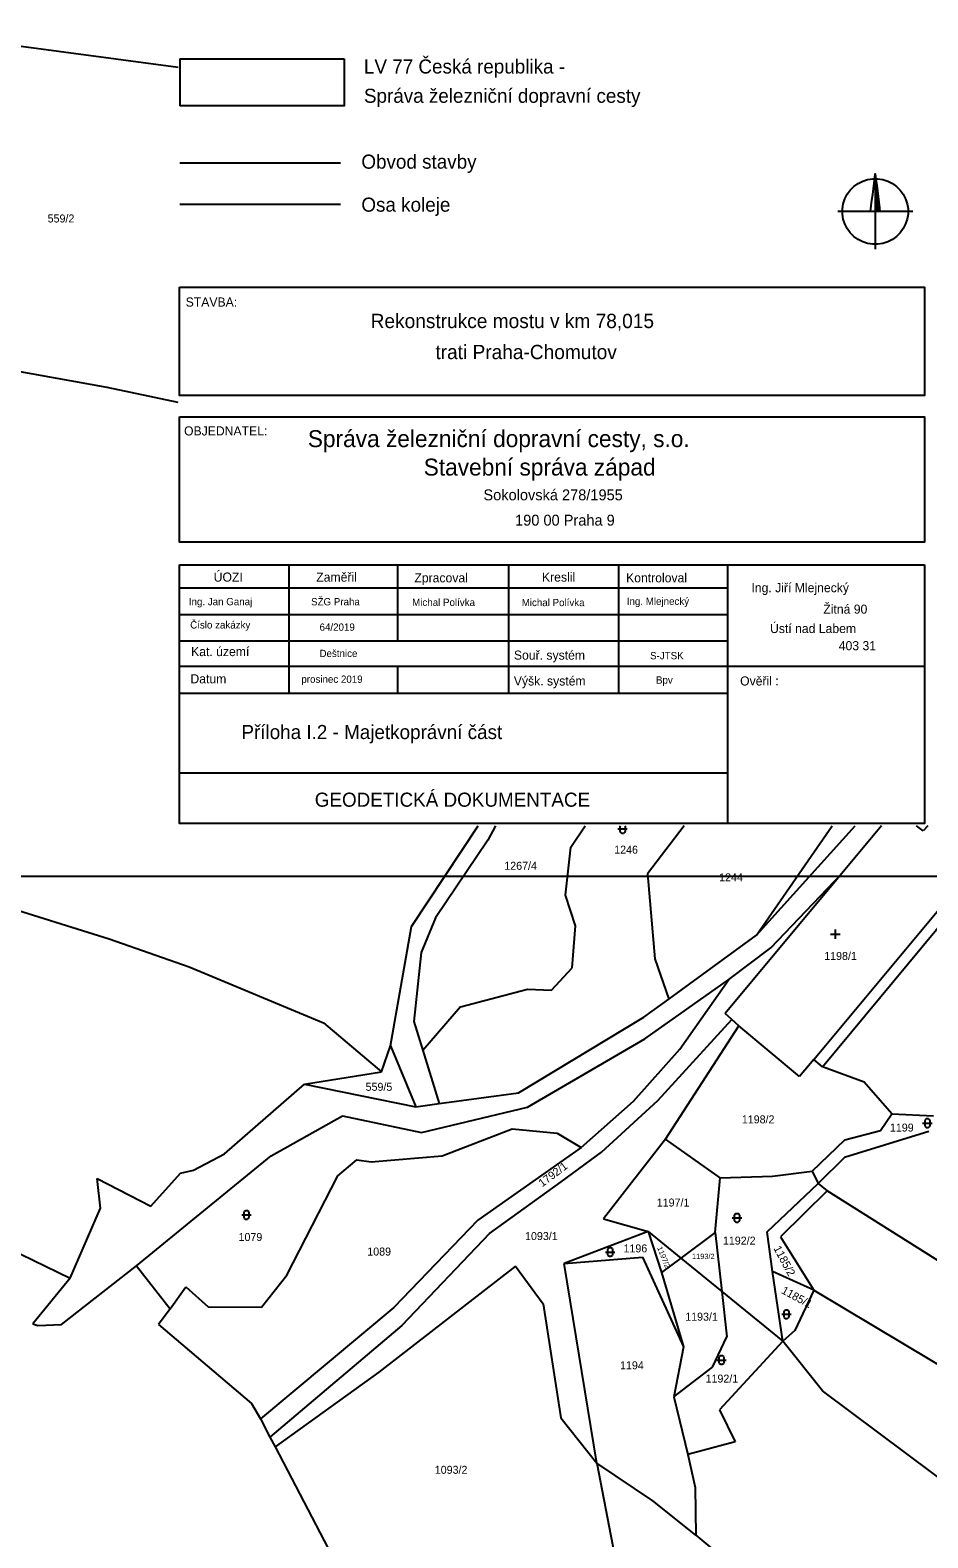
# Model space of a CAD drawing. Extents: x -799786 to -795190, y -1021716 to -1017834.
# Drawn here: x -798625.3 to -798434.2, y -1019350.1 to -1019029 of the extents above; entities that cross this region are included whole.
import ezdxf

# ---------------------------------------------------------------- set-up
doc = ezdxf.new("R2010")
doc.units = 0
for name, color, linetype in [('Default', 7, 'Continuous'), ('KN_HRANICE', 7, 'Continuous'), ('KN_KULTURY', 7, 'Continuous'), ('KN_PARCELY', 7, 'Continuous'), ('LEGENDA', 7, 'Continuous'), ('tabulka', 7, 'Continuous')]:
    doc.layers.add(name, color=color, linetype=linetype)

# ---------------------------------------------------------------- blocks, each defined once
blk = doc.blocks.new('315')
at = {"layer": 'Default'}
for p, q in [((-1, 1), (1, 1)), ((0, 0), (0, 2))]:
    blk.add_line(p, q, dxfattribs=at)
blk = doc.blocks.new('316')
at = {"layer": 'Default'}
for points in [[(-1, 1), (0.27, 1), (1, 1)], [(-0.5, 1.5), (-0.4, 1.79), (-0.15, 1.97), (0.16, 1.97), (0.41, 1.79), (0.51, 1.5), (0.51, 0.5), (0.41, 0.21), (0.16, 0.03), (-0.15, 0.03), (-0.4, 0.21), (-0.5, 0.5), (-0.5, 1.5)]]:
    blk.add_lwpolyline(points, dxfattribs=at)
blk = doc.blocks.new('SEVER')
at = {"layer": 'Default'}
for points in [[(5.5, 69.8), (16.3, 68.1), (26.7, 64.7), (36.5, 59.7), (45.4, 53.2), (53.2, 45.4), (59.7, 36.5), (64.7, 26.7), (68.1, 16.3), (69.8, 5.5), (69.8, -5.5), (68.1, -16.3), (64.7, -26.7), (59.7, -36.5), (53.2, -45.4), (45.4, -53.2), (36.5, -59.7), (26.7, -64.7), (16.3, -68.1), (5.5, -69.8), (-5.5, -69.8), (-16.3, -68.1), (-26.7, -64.7), (-36.5, -59.7), (-45.4, -53.2), (-53.2, -45.4), (-59.7, -36.5), (-64.7, -26.7), (-68.1, -16.3), (-69.8, -5.5), (-69.8, 5.5), (-68.1, 16.3), (-64.7, 26.7), (-59.7, 36.5), (-53.2, 45.4), (-45.4, 53.2), (-36.5, 59.7), (-26.7, 64.7), (-16.3, 68.1), (-5.5, 69.8), (5.5, 69.8)], [(-10, 0), (-8.5, 12), (-7, 24), (-5.5, 36), (-4, 48), (-2.5, 60), (-1, 72), (0, 80), (1.5, 68), (3, 56), (4.5, 44), (6, 32), (7.5, 20), (9, 8), (10, 0), (9.2, 0.8), (9.2, 5.6), (8.4, 12), (8.4, 0.8), (7.6, 0.8), (7.6, 13.5), (7.6, 18.4), (6.8, 24.8), (6.8, 12.1), (6.8, 0.8), (6, 0.8), (6, 13.5), (6, 26.2), (6, 31.2), (5.2, 36.8), (5.2, 24.1), (5.2, 11.4), (5.2, 0.8), (4.4, 0.8), (4.4, 13.5), (4.4, 26.2), (4.4, 38.9), (4.4, 43.2), (3.6, 50.4), (3.6, 37.7), (3.6, 25), (3.6, 12.3), (3.6, 0.8), (2.8, 0.8), (2.8, 13.5), (2.8, 26.2), (2.8, 38.9), (2.8, 51.6), (2.8, 56), (2, 63.2), (2, 50.5), (2, 37.8), (2, 25.1), (2, 12.4), (2, 0.8), (1.2, 0.8), (1.2, 13.5), (1.2, 26.2), (1.2, 38.9), (1.2, 51.6), (1.2, 64.3), (1.2, 69.6), (0.4, 76), (0.4, 63.3), (0.4, 50.6), (0.4, 37.9), (0.4, 25.2), (0.4, 12.5), (0.4, 0.8)], [(0, 80), (0, 67.3), (0, 54.6), (0, 41.9), (0, 29.2), (0, 16.5), (0, 3.8), (0, -8.9), (0, -21.6), (0, -34.3), (0, -47), (0, -59.7), (0, -72.4), (0, -80)], [(80, 0), (67.3, 0), (54.6, 0), (41.9, 0), (29.2, 0), (16.5, 0), (3.8, 0), (-8.9, 0), (-21.6, 0), (-34.3, 0), (-47, 0), (-59.7, 0), (-72.4, 0), (-80, 0)]]:
    blk.add_lwpolyline(points, dxfattribs=at)

msp = doc.modelspace()

# ---------------------------------------------------------------- linework, layer by layer
at = {"layer": 'KN_HRANICE'}
for p, q in [((-798650, -1019029.38), (-798593.84, -1019036.93)), ((-798608.96, -1019105.11), (-798639.62, -1019099.64)), ((-798593.84, -1019108.35), (-798608.96, -1019105.11)), ((-798544.17, -1019219.92), (-798529.93, -1019198.47)), ((-798526.27, -1019198.47), (-798527.91, -1019201.56)), ((-798510.21, -1019203), (-798507.21, -1019198.47)), ((-798486.07, -1019198.47), (-798493.93, -1019208.72)), ((-798470.68, -1019221.78), (-798449.69, -1019198.47)), ((-798470.68, -1019221.78), (-798454.57, -1019198.47)), ((-798444.09, -1019198.47), (-798452.63, -1019208.73)), ((-798435.21, -1019199.56), (-798436.61, -1019198.47)), ((-798434.24, -1019198.47), (-798435.21, -1019199.56)), ((-798527.91, -1019201.56), (-798539.04, -1019218.08)), ((-798511.35, -1019213.22), (-798510.21, -1019203)), ((-798493.93, -1019208.72), (-798492.37, -1019226.82)), ((-798452.63, -1019208.73), (-798477.35, -1019238.45)), ((-798467.68, -1019224.43), (-798452.63, -1019208.73)), ((-798458.53, -1019248.28), (-798425.19, -1019208.25)), ((-798641.03, -1019212.36), (-798608.55, -1019222.56)), ((-798509.26, -1019219.75), (-798511.35, -1019213.22)), ((-798456.62, -1019249.78), (-798429.28, -1019216.81)), ((-798548.65, -1019245.36), (-798544.17, -1019219.92)), ((-798539.04, -1019218.08), (-798542.11, -1019225.49)), ((-798509.93, -1019228.7), (-798509.26, -1019219.75)), ((-798608.55, -1019222.56), (-798591.52, -1019228.5)), ((-798489.36, -1019235.41), (-798470.68, -1019221.78)), ((-798542.11, -1019225.49), (-798543.64, -1019240.18)), ((-798476.58, -1019231.21), (-798467.68, -1019224.43)), ((-798591.52, -1019228.5), (-798562.92, -1019240.42)), ((-798514.33, -1019233.5), (-798509.93, -1019228.7)), ((-798492.37, -1019226.82), (-798489.36, -1019235.41)), ((-798494.5, -1019243.85), (-798476.58, -1019231.21)), ((-798487.05, -1019246.02), (-798476.58, -1019231.21)), ((-798533.7, -1019237.04), (-798519.48, -1019233.3)), ((-798519.48, -1019233.3), (-798514.33, -1019233.5)), ((-798494.71, -1019239.22), (-798489.36, -1019235.41)), ((-798533.7, -1019237.04), (-798541.71, -1019246.33)), ((-798521.41, -1019255.32), (-798494.71, -1019239.22)), ((-798475.96, -1019239.74), (-798477.35, -1019238.45)), ((-798562.92, -1019240.42), (-798550.57, -1019250.84)), ((-798543.64, -1019240.18), (-798541.71, -1019246.33)), ((-798491.71, -1019256.99), (-798475.96, -1019239.74)), ((-798490.05, -1019265.19), (-798474.46, -1019241.09)), ((-798474.46, -1019241.09), (-798475.96, -1019239.74)), ((-798461.53, -1019251.9), (-798474.46, -1019241.09)), ((-798550.57, -1019250.84), (-798548.65, -1019245.36)), ((-798548.65, -1019245.36), (-798543.24, -1019258.32)), ((-798519.48, -1019258.39), (-798494.5, -1019243.85)), ((-798496.88, -1019257.09), (-798487.05, -1019246.02)), ((-798541.71, -1019246.33), (-798538.3, -1019257.65)), ((-798458.53, -1019248.28), (-798461.53, -1019251.9)), ((-798456.62, -1019249.78), (-798458.53, -1019248.28)), ((-798566.93, -1019253.51), (-798550.57, -1019250.84)), ((-798447.78, -1019253.09), (-798456.62, -1019249.78)), ((-798583.99, -1019268.34), (-798566.93, -1019253.51)), ((-798566.93, -1019253.51), (-798543.24, -1019258.32)), ((-798538.3, -1019257.65), (-798521.41, -1019255.32)), ((-798441.91, -1019259.81), (-798447.78, -1019253.09)), ((-798543.24, -1019258.32), (-798538.3, -1019257.65)), ((-798542.02, -1019263.8), (-798519.48, -1019258.39)), ((-798508.04, -1019267.02), (-798496.88, -1019257.09)), ((-798503.7, -1019267.95), (-798491.71, -1019256.99)), ((-798574.04, -1019268.76), (-798558.85, -1019260.26)), ((-798558.85, -1019260.26), (-798542.02, -1019263.8)), ((-798444.34, -1019263.37), (-798441.91, -1019259.81)), ((-798441.91, -1019259.81), (-798433.02, -1019260.22)), ((-798537.62, -1019268.78), (-798522.73, -1019262.99)), ((-798522.73, -1019262.99), (-798513.11, -1019263.92)), ((-798513.11, -1019263.92), (-798508.04, -1019267.02)), ((-798490.05, -1019265.19), (-798503.28, -1019282.16)), ((-798478.47, -1019273.47), (-798490.05, -1019265.19)), ((-798434, -1019263.58), (-798451.99, -1019269.12)), ((-798451.89, -1019265.39), (-798444.34, -1019263.37)), ((-798590.6, -1019271.84), (-798583.99, -1019268.34)), ((-798508.04, -1019267.02), (-798530.05, -1019282.48)), ((-798512.26, -1019274.31), (-798503.7, -1019267.95)), ((-798458.82, -1019272.01), (-798451.89, -1019265.39)), ((-798602.68, -1019292.18), (-798574.04, -1019268.76)), ((-798559.85, -1019273.02), (-798555.82, -1019269.61)), ((-798555.82, -1019269.61), (-798552.72, -1019270.02)), ((-798552.72, -1019270.02), (-798537.62, -1019268.78)), ((-798451.99, -1019269.12), (-798457.57, -1019274.65)), ((-798610.36, -1019279.89), (-798611.08, -1019273.6)), ((-798611.08, -1019273.6), (-798599.68, -1019279.49)), ((-798599.68, -1019279.49), (-798593.31, -1019272.48)), ((-798593.31, -1019272.48), (-798590.6, -1019271.84)), ((-798570.69, -1019294.19), (-798559.85, -1019273.02)), ((-798527.56, -1019285.28), (-798512.26, -1019274.31)), ((-798479.53, -1019285.1), (-798478.47, -1019273.47)), ((-798478.47, -1019273.47), (-798467.29, -1019273.1)), ((-798468.41, -1019284.95), (-798457.57, -1019274.65)), ((-798467.29, -1019273.1), (-798458.82, -1019272.01)), ((-798458.82, -1019272.01), (-798457.57, -1019274.65)), ((-798457.57, -1019274.65), (-798455.66, -1019276.2)), ((-798653.35, -1019277.09), (-798616.8, -1019294.82)), ((-798455.66, -1019276.2), (-798465.62, -1019286.03)), ((-798413.87, -1019302.58), (-798455.66, -1019276.2)), ((-798616.8, -1019294.82), (-798610.36, -1019279.89)), ((-798530.05, -1019282.48), (-798547.93, -1019301.1)), ((-798503.28, -1019282.16), (-798493.77, -1019284.85)), ((-798527.56, -1019285.28), (-798546.18, -1019304.93)), ((-798493.77, -1019284.85), (-798511.66, -1019291.68)), ((-798493.77, -1019284.85), (-798490.9, -1019293.64)), ((-798493.77, -1019284.85), (-798486.8, -1019290.56)), ((-798479.53, -1019285.1), (-798486.8, -1019290.56)), ((-798479.53, -1019285.1), (-798478.12, -1019297.69)), ((-798467.32, -1019293.43), (-798468.41, -1019284.95)), ((-798465.62, -1019286.03), (-798458.48, -1019297.36)), ((-798511.66, -1019291.68), (-798495.01, -1019290.33)), ((-798495.01, -1019290.33), (-798486.25, -1019309.47)), ((-798486.8, -1019290.56), (-798490.9, -1019293.64)), ((-798486.8, -1019290.56), (-798478.12, -1019297.69)), ((-798618.7, -1019304.72), (-798602.68, -1019292.18)), ((-798602.68, -1019292.18), (-798595.52, -1019301.34)), ((-798576.06, -1019301.02), (-798570.69, -1019294.19)), ((-798521.98, -1019292.29), (-798551.14, -1019314.85)), ((-798521.98, -1019292.29), (-798516.09, -1019300.26)), ((-798504.73, -1019334.25), (-798511.66, -1019291.68)), ((-798490.9, -1019293.64), (-798486.25, -1019309.47)), ((-798458.48, -1019297.36), (-798467.32, -1019293.43)), ((-798465.13, -1019308.25), (-798467.32, -1019293.43)), ((-798616.8, -1019294.82), (-798624.76, -1019304.52)), ((-798595.52, -1019301.34), (-798592.23, -1019296.66)), ((-798592.23, -1019296.66), (-798587.44, -1019300.91)), ((-798458.48, -1019297.36), (-798462.51, -1019305.95)), ((-798458.48, -1019297.36), (-798422.2, -1019319.14)), ((-798516.09, -1019300.26), (-798512.36, -1019324.57)), ((-798478.12, -1019297.69), (-798477.04, -1019307.29)), ((-798478.12, -1019297.69), (-798465.13, -1019308.25)), ((-798595.52, -1019301.34), (-798598, -1019304.72)), ((-798587.44, -1019300.91), (-798576.06, -1019301.02)), ((-798547.93, -1019301.1), (-798576.33, -1019324.79)), ((-798624.76, -1019304.52), (-798623.72, -1019304.92)), ((-798623.72, -1019304.92), (-798618.7, -1019304.72)), ((-798598, -1019304.72), (-798578.22, -1019321.5)), ((-798546.18, -1019304.93), (-798574.35, -1019328.67)), ((-798462.51, -1019305.95), (-798465.13, -1019308.25)), ((-798486.25, -1019309.47), (-798488.31, -1019320.12)), ((-798480.09, -1019313.76), (-798477.04, -1019307.29)), ((-798465.13, -1019308.25), (-798478.57, -1019322.88)), ((-798456.65, -1019318.8), (-798465.13, -1019308.25)), ((-798551.14, -1019314.85), (-798573.15, -1019330.76)), ((-798488.31, -1019320.12), (-798480.09, -1019313.76)), ((-798422.56, -1019344.32), (-798456.65, -1019318.8)), ((-798578.22, -1019321.5), (-798576.33, -1019324.79)), ((-798488.31, -1019320.12), (-798485.29, -1019332.39)), ((-798478.57, -1019322.88), (-798475.26, -1019329.7)), ((-798576.33, -1019324.79), (-798574.35, -1019328.67)), ((-798512.36, -1019324.57), (-798504.73, -1019334.25)), ((-798574.35, -1019328.67), (-798573.15, -1019330.76)), ((-798573.15, -1019330.76), (-798558.55, -1019358.8)), ((-798475.26, -1019329.7), (-798485.29, -1019332.39)), ((-798485.29, -1019332.39), (-798483.74, -1019339.43)), ((-798504.73, -1019334.25), (-798500.11, -1019358.06)), ((-798492.74, -1019342.22), (-798504.73, -1019334.25)), ((-798483.64, -1019349.57), (-798492.74, -1019342.22)), ((-798483.74, -1019339.43), (-798483.64, -1019349.57)), ((-798483.64, -1019349.57), (-798468.64, -1019361.98))]:
    msp.add_line(p, q, dxfattribs=at)
at = {"layer": 'KN_KULTURY'}
for points in [[(-798500.21, -1019199.11), (-798498.94, -1019199.11), (-798498.21, -1019199.11)], [(-798499.71, -1019198.61), (-798499.66, -1019198.47)], [(-798498.75, -1019198.47), (-798498.7, -1019198.61), (-798498.7, -1019199.61), (-798498.8, -1019199.9), (-798499.05, -1019200.08), (-798499.36, -1019200.08), (-798499.61, -1019199.9), (-798499.71, -1019199.61), (-798499.71, -1019198.61)]]:
    msp.add_lwpolyline(points, dxfattribs=at)
at = {"layer": 'LEGENDA'}
for p, q in [((-798593.5, -1019035.14), (-798558.5, -1019035.14)), ((-798593.5, -1019035.14), (-798593.5, -1019045.14)), ((-798593.48, -1019057.27), (-798559.28, -1019057.27)), ((-798593.48, -1019066.1), (-798559.28, -1019066.1))]:
    msp.add_line(p, q, dxfattribs=at)
msp.add_lwpolyline([(-799014.18, -1018789.26), (-798420.18, -1018789.26), (-798420.18, -1019209.26), (-799014.18, -1019209.26)], close=True, dxfattribs=at)
msp.add_lwpolyline([(-798558.5, -1019035.14), (-798558.5, -1019045.14), (-798593.5, -1019045.14)], dxfattribs=at)
at = {"layer": 'tabulka'}
for p, q in [((-798593.57, -1019142.87), (-798434.91, -1019142.87)), ((-798570.28, -1019142.87), (-798570.28, -1019170.19)), ((-798547.13, -1019142.87), (-798547.13, -1019159.07)), ((-798523.53, -1019142.87), (-798523.53, -1019170.19)), ((-798500.09, -1019142.87), (-798500.09, -1019170.19)), ((-798476.79, -1019198), (-798476.79, -1019142.87)), ((-798593.57, -1019147.77), (-798476.79, -1019147.77)), ((-798593.57, -1019153.49), (-798476.79, -1019153.49)), ((-798593.57, -1019159.07), (-798476.79, -1019159.07)), ((-798593.57, -1019164.49), (-798434.91, -1019164.49)), ((-798547.13, -1019164.49), (-798547.13, -1019170.19)), ((-798593.57, -1019170.19), (-798476.79, -1019170.19)), ((-798593.57, -1019187.18), (-798476.79, -1019187.18))]:
    msp.add_line(p, q, dxfattribs=at)
for points in [[(-798593.57, -1019083.78), (-798434.91, -1019083.78), (-798434.91, -1019106.84), (-798593.57, -1019106.84)], [(-798593.57, -1019111.36), (-798434.91, -1019111.36), (-798434.91, -1019138.06), (-798593.57, -1019138.06)]]:
    msp.add_lwpolyline(points, close=True, dxfattribs=at)
msp.add_lwpolyline([(-798434.91, -1019142.87), (-798434.91, -1019198), (-798593.57, -1019198), (-798593.57, -1019142.87)], dxfattribs=at)

# ---------------------------------------------------------------- block references
at = {"layer": 'KN_KULTURY'}
for name, p in [('315', (-798453.92, -1019222.56)), ('316', (-798434.33, -1019262.8)), ('316', (-798579.31, -1019282.35)), ('316', (-798474.86, -1019282.99)), ('316', (-798501.87, -1019290.25)), ('316', (-798464.34, -1019303.51)), ('316', (-798478.16, -1019313.27))]:
    msp.add_blockref(name, p, dxfattribs=at)
at = {"layer": 'LEGENDA', "xscale": 0.1, "yscale": 0.10000000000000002}
msp.add_blockref('SEVER', (-798445.42, -1019067.63), dxfattribs=at)

# ---------------------------------------------------------------- texts
at = {"layer": 'KN_PARCELY'}
for s, height, p in [('559/2', 1.7, (-798621.62, -1019069.97)), ('1246', 1.7, (-798501, -1019204.41)), ('1267/4', 1.7, (-798524.4, -1019207.84)), ('1244', 1.7, (-798478.66, -1019210.29)), ('1198/1', 1.7, (-798456.29, -1019227.05)), ('559/5', 1.7, (-798553.93, -1019254.91)), ('1198/2', 1.7, (-798473.83, -1019261.85)), ('1199', 1.7, (-798442.3, -1019263.6)), ('1197/1', 1.7, (-798491.94, -1019279.56)), ('1079', 1.7, (-798580.98, -1019286.9)), ('1093/1', 1.7, (-798519.98, -1019286.7)), ('1196', 1.7, (-798499.02, -1019289.33)), ('1192/2', 1.7, (-798477.86, -1019287.67)), ('1089', 1.7, (-798553.57, -1019290)), ('1193/2', 1.14, (-798484.44, -1019290.75)), ('1193/1', 1.7, (-798485.88, -1019303.88)), ('1194', 1.7, (-798499.76, -1019314.23)), ('1192/1', 1.7, (-798481.55, -1019317.06)), ('1093/2', 1.7, (-798539.2, -1019336.48))]:
    msp.add_text(s, height=height, dxfattribs=at).set_placement(p)
for s, height, rotation, p in [('1792/1', 1.7, 36.956, (-798516.31, -1019275.48)), ('1197/2', 1.14, 292.037, (-798491.89, -1019288.34)), ('1185/2', 1.7, 298.282, (-798467.14, -1019288.46)), ('1185/1', 1.7, 331.399, (-798465.55, -1019297.94))]:
    msp.add_text(s, height=height, rotation=rotation, dxfattribs=at).set_placement(p)
at = {"layer": 'LEGENDA'}
for s, p in [('LV 77 Česká republika -', (-798554.28, -1019038.25)), ('Správa železniční dopravní cesty', (-798554.28, -1019044.49)), ('Obvod stavby', (-798554.83, -1019058.52)), ('Osa koleje', (-798554.83, -1019067.68))]:
    msp.add_text(s, height=3, dxfattribs=at).set_placement(p)
at = {"layer": 'tabulka'}
for s, height, p in [('STAVBA:', 1.94, (-798592.23, -1019087.89)), ('Rekonstrukce mostu v km 78,015', 3.04, (-798552.85, -1019092.47)), ('trati Praha-Chomutov', 3.04, (-798539.07, -1019099.08)), ('OBJEDNATEL:', 1.94, (-798592.58, -1019115.34)), ('Správa železniční dopravní cesty, s.o.', 3.61, (-798566.23, -1019117.82)), ('Stavební správa západ', 3.61, (-798541.56, -1019123.88)), ('Sokolovská 278/1955', 2.32, (-798528.84, -1019129.15)), ('190 00 Praha 9', 2.32, (-798522.1, -1019134.54)), ('ÚOZI', 1.94, (-798586.27, -1019146.47)), ('Zaměřil', 1.94, (-798564.43, -1019146.47)), ('Zpracoval', 1.94, (-798543.54, -1019146.62)), ('Kreslil', 1.94, (-798516.38, -1019146.47)), ('Kontroloval', 1.94, (-798498.47, -1019146.62)), ('SŽG Praha', 1.552, (-798565.54, -1019151.53)), ('Ing. Jiří Mlejnecký', 1.94, (-798471.78, -1019148.73)), ('Ing. Jan Ganaj', 1.552, (-798591.56, -1019151.5)), ('Michal Polívka', 1.552, (-798544.02, -1019151.65)), ('Michal Polívka', 1.552, (-798520.69, -1019151.69)), ('Ing. Mlejnecký', 1.552, (-798498.32, -1019151.42)), ('Žitná 90', 1.94, (-798456.48, -1019153.3)), ('Číslo zakázky', 1.552, (-798591.27, -1019156.45)), ('64/2019', 1.552, (-798563.73, -1019156.93)), ('Ústí nad Labem', 1.94, (-798467.82, -1019157.42)), ('403 31', 1.94, (-798453.19, -1019161.08)), ('Kat. území', 1.94, (-798591.08, -1019162.33)), ('Deštnice', 1.552, (-798563.74, -1019162.53)), ('Souř. systém', 1.94, (-798522.35, -1019163.09)), ('S-JTSK', 1.552, (-798493.36, -1019163.01)), ('Datum', 1.94, (-798591.22, -1019168.13)), ('prosinec 2019', 1.552, (-798567.6, -1019168.02)), ('Výšk. systém', 1.94, (-798522.37, -1019168.59)), ('Bpv', 1.552, (-798492.1, -1019168.2)), ('Ověřil :', 1.94, (-798474.19, -1019168.59)), ('Příloha I.2 - Majetkoprávní část', 3, (-798580.36, -1019180)), ('GEODETICKÁ DOKUMENTACE ', 3, (-798564.75, -1019194.41))]:
    msp.add_text(s, height=height, dxfattribs=at).set_placement(p)

doc.saveas('drawing.dxf')
